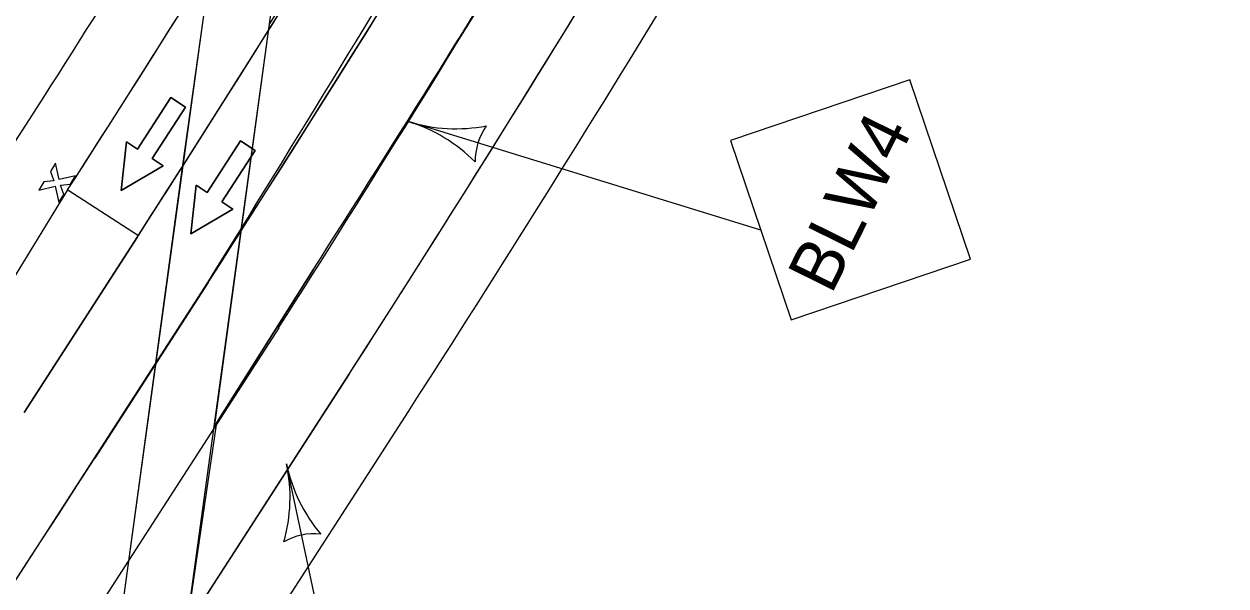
# Model space of a CAD drawing. Extents: x 14097936 to 14128734, y 8632000 to 8683104.
# Drawn here: x 14119491.1 to 14119662.5, y 8669393 to 8669473.1 of the extents above; entities that cross this region are included whole.
import ezdxf

# ---------------------------------------------------------------- set-up
doc = ezdxf.new("R2010")
doc.units = 0
for name, color, linetype in [('Cell', 7, 'Continuous'), ('dsn_stg_shd_prev', 7, 'Continuous'), ('dsnPaintPlaceBrokenLaneWhite', 7, 'Continuous'), ('dsnPaintPlaceDoubleCenterLineYellow', 7, 'Continuous'), ('dsnPaintPlaceEdgeLineRightWhite', 7, 'Continuous'), ('dsnShadingPaved', 7, 'Continuous'), ('dsnStdLabel', 7, 'Continuous'), ('dsnStgShadingPropPav', 7, 'Continuous'), ('dsnTapePlaceChannelizingLaneWhite', 7, 'Continuous'), ('Level 2', 7, 'Continuous'), ('Level 5', 7, 'Continuous')]:
    doc.layers.add(name, color=color, linetype=linetype)

msp = doc.modelspace()

# ---------------------------------------------------------------- linework, layer by layer
at = {"layer": 'Cell'}
for p, q in [((14119495.63, 8669453.27), (14119494.89, 8669452.11)), ((14119496.15, 8669450.94), (14119495.63, 8669453.27)), ((14119494.89, 8669452.11), (14119495.37, 8669450.76)), ((14119498.48, 8669451.46), (14119496.15, 8669450.94)), ((14119497.74, 8669450.3), (14119498.48, 8669451.46)), ((14119493.95, 8669450.63), (14119493.22, 8669449.46)), ((14119493.22, 8669449.46), (14119495.55, 8669449.99)), ((14119495.37, 8669450.76), (14119493.95, 8669450.63)), ((14119495.55, 8669449.99), (14119496.07, 8669447.66)), ((14119496.32, 8669450.16), (14119497.74, 8669450.3)), ((14119496.81, 8669448.82), (14119496.32, 8669450.16)), ((14119496.07, 8669447.66), (14119496.81, 8669448.82))]:
    msp.add_line(p, q, dxfattribs=at)
at = {"layer": 'dsn_stg_shd_prev'}
msp.add_line((14119518.27, 8669415.59), (14119526.14, 8669473.13), dxfattribs=at)
for points in [[(14119532.34, 8669438.08), (14119518.3, 8669415.78), (14119518.27, 8669415.59)], [(14119518.63, 8669416.31), (14119532.34, 8669438.08)], [(14119545.92, 8669417.86), (14119510.41, 8669362.84), (14119514.62, 8669389.1), (14119518.63, 8669416.31)]]:
    msp.add_lwpolyline(points, dxfattribs=at)
for centre, radius, start, end in [((14117131.57, 8670975.38), 2826.79, 327.89779, 330.07663), ((14117131.57, 8670975.38), 2850.79, 327.36717, 330.07636), ((14117131.57, 8670975.38), 2850.79, 327.36717, 330.07636), ((14117116.55, 8670981.01), 2888.83, 327.24115, 330.12784)]:
    msp.add_arc(centre, radius, start, end, dxfattribs=at)
at = {"layer": 'dsnPaintPlaceBrokenLaneWhite'}
msp.add_line((14119527.44, 8669429.79), (14119185.09, 8668899.43), dxfattribs=at)
for centre, radius, start, end in [((14117116.91, 8670980.36), 2842.2, 327.25475, 330.13693), ((14116764.68, 8671186.54), 3273.99, 327.54894, 330.07644)]:
    msp.add_arc(centre, radius, start, end, dxfattribs=at)
at = {"layer": 'dsnPaintPlaceDoubleCenterLineYellow'}
msp.add_line((14119477.17, 8669374.04), (14119517.35, 8669436.29), dxfattribs=at)
msp.add_arc((14113624.84, 8673081.81), 6929.04, 328.256149, 329.445383, dxfattribs=at)
at = {"layer": 'dsnPaintPlaceEdgeLineRightWhite'}
msp.add_line((14119195.17, 8668892.92), (14119537.53, 8669423.29), dxfattribs=at)
for centre, radius, start, end in [((14117116.91, 8670980.36), 2830.2, 327.25475, 330.13732), ((14117117.1, 8670980.68), 2878.19, 327.24148, 330.12846)]:
    msp.add_arc(centre, radius, start, end, dxfattribs=at)
at = {"layer": 'dsnShadingPaved'}
for p, q in [((14119497.35, 8669449.49), (14119507.43, 8669442.98)), ((14119497.35, 8669449.49), (14119507.43, 8669442.98)), ((14119491.13, 8669417.73), (14119507.3, 8669442.79)), ((14119507.3, 8669442.79), (14119491.13, 8669417.73)), ((14119175.01, 8668905.94), (14119517.35, 8669436.29)), ((14119517.39, 8669436.29), (14119501.21, 8669411.22))]:
    msp.add_line(p, q, dxfattribs=at)
msp.add_lwpolyline([(14119502.19, 8669368.54), (14119514.34, 8669387.38), (14119530.03, 8669501.55), (14119517.74, 8669481.68)], close=True, dxfattribs=at)
for points in [[(14119238.52, 8669044.85), (14119265.99, 8669086.65), (14119293.47, 8669128.44), (14119320.94, 8669170.24), (14119348.3, 8669212.11), (14119375.45, 8669254.16), (14119402.36, 8669296.35), (14119429.03, 8669338.69), (14119455.46, 8669381.17), (14119481.65, 8669423.79), (14119497.35, 8669449.49)], [(14119537.53, 8669423.29), (14119537.53, 8669423.29), (14119195.17, 8668892.92)]]:
    msp.add_lwpolyline(points, dxfattribs=at)
for centre, radius, start, end in [((14117116.91, 8670980.36), 2830.2, 327.25475, 332.18395), ((14117116.91, 8670980.36), 2842.2, 327.24958, 332.18395), ((14117116.91, 8670980.36), 2842.2, 327.25434, 332.18395), ((14117117.1, 8670980.68), 2854.19, 327.24165, 332.17585), ((14117116.91, 8670980.36), 2854.2, 327.24958, 332.18395), ((14117117.1, 8670980.68), 2878.19, 327.24148, 332.17585), ((14117116.91, 8670980.36), 2842.2, 327.24958, 327.25434), ((14111929.66, 8674298.73), 9012, 325.249705, 327.157368)]:
    msp.add_arc(centre, radius, start, end, dxfattribs=at)
at = {"layer": 'dsnStdLabel'}
for p, q in [((14119596.2, 8669443.75), (14119545.93, 8669459.22)), ((14119539.17, 8669360.24), (14119528.56, 8669410.39))]:
    msp.add_line(p, q, dxfattribs=at)
msp.add_lwpolyline([(14119600.53, 8669430.96), (14119626.1, 8669439.61), (14119617.45, 8669465.19), (14119591.87, 8669456.54)], close=True, dxfattribs=at)
for centre, radius, start, end in [((14119539.18, 8669437.28), 22.95, 44.8209, 72.8923), ((14119552.69, 8669481.15), 22.95, 252.8921, 280.9634), ((14119564.32, 8669453.56), 8.86, 145.1579, 180.6264), ((14119506.11, 8669405.64), 22.95, 343.8726, 11.9439), ((14119551.01, 8669415.14), 22.95, 191.9437, 220.015), ((14119532.54, 8669391.57), 8.86, 84.2095, 119.678)]:
    msp.add_arc(centre, radius, start, end, dxfattribs=at)
at = {"layer": 'dsnStgShadingPropPav'}
msp.add_line((14119518.27, 8669415.59), (14119526.14, 8669473.13), dxfattribs=at)
for points in [[(14119521.18, 8669506.24), (14119513.69, 8669452.68), (14119513.69, 8669452.69), (14119501.63, 8669364.46)], [(14119532.34, 8669438.08), (14119518.3, 8669415.78), (14119518.27, 8669415.59)], [(14119518.63, 8669416.31), (14119532.34, 8669438.08)], [(14119545.92, 8669417.86), (14119510.41, 8669362.84), (14119514.62, 8669389.1), (14119518.63, 8669416.31)]]:
    msp.add_lwpolyline(points, dxfattribs=at)
for centre, radius, start, end in [((14117131.57, 8670975.38), 2826.79, 327.89779, 330.07663), ((14117131.57, 8670975.38), 2826.79, 327.89779, 330.07663), ((14117131.57, 8670975.38), 2850.79, 327.36717, 330.07636), ((14117131.57, 8670975.38), 2850.79, 327.36717, 330.07636), ((14117116.55, 8670981.01), 2888.83, 327.24115, 330.12784), ((14117116.91, 8670980.36), 2820.2, 327.24978, 328.48633)]:
    msp.add_arc(centre, radius, start, end, dxfattribs=at)
at = {"layer": 'dsnTapePlaceChannelizingLaneWhite'}
msp.add_lwpolyline([(14119238.52, 8669044.85), (14119265.99, 8669086.65), (14119293.47, 8669128.44), (14119320.94, 8669170.24), (14119348.3, 8669212.11), (14119375.45, 8669254.16), (14119402.36, 8669296.35), (14119429.03, 8669338.69), (14119455.46, 8669381.17), (14119481.65, 8669423.79), (14119497.35, 8669449.49)], dxfattribs=at)
at = {"layer": 'Level 2'}
for points in [[(14119514.15, 8669461.29), (14119512.05, 8669462.65), (14119507.31, 8669455.3), (14119505.73, 8669456.31), (14119504.97, 8669449.37), (14119510.98, 8669452.92), (14119509.41, 8669453.94)], [(14119524.09, 8669455.11), (14119521.99, 8669456.47), (14119517.24, 8669449.12), (14119515.67, 8669450.13), (14119514.9, 8669443.19), (14119520.92, 8669446.74), (14119519.34, 8669447.76)]]:
    msp.add_lwpolyline(points, close=True, dxfattribs=at)
at = {"layer": 'Level 5'}
for points in [[(14119509.41, 8669453.94), (14119510.98, 8669452.92), (14119504.97, 8669449.37), (14119505.73, 8669456.31), (14119507.31, 8669455.3), (14119512.05, 8669462.65), (14119514.15, 8669461.29), (14119509.41, 8669453.94)], [(14119519.34, 8669447.76), (14119520.92, 8669446.74), (14119514.9, 8669443.19), (14119515.67, 8669450.13), (14119517.24, 8669449.12), (14119521.99, 8669456.47), (14119524.09, 8669455.11), (14119519.34, 8669447.76)]]:
    msp.add_lwpolyline(points, dxfattribs=at)

# ---------------------------------------------------------------- texts
at = {"layer": 'dsnStdLabel'}
msp.add_text('BLW4', height=7.2, rotation=63.6912, dxfattribs=at).set_placement((14119606.25, 8669434.42))

doc.saveas('drawing.dxf')
